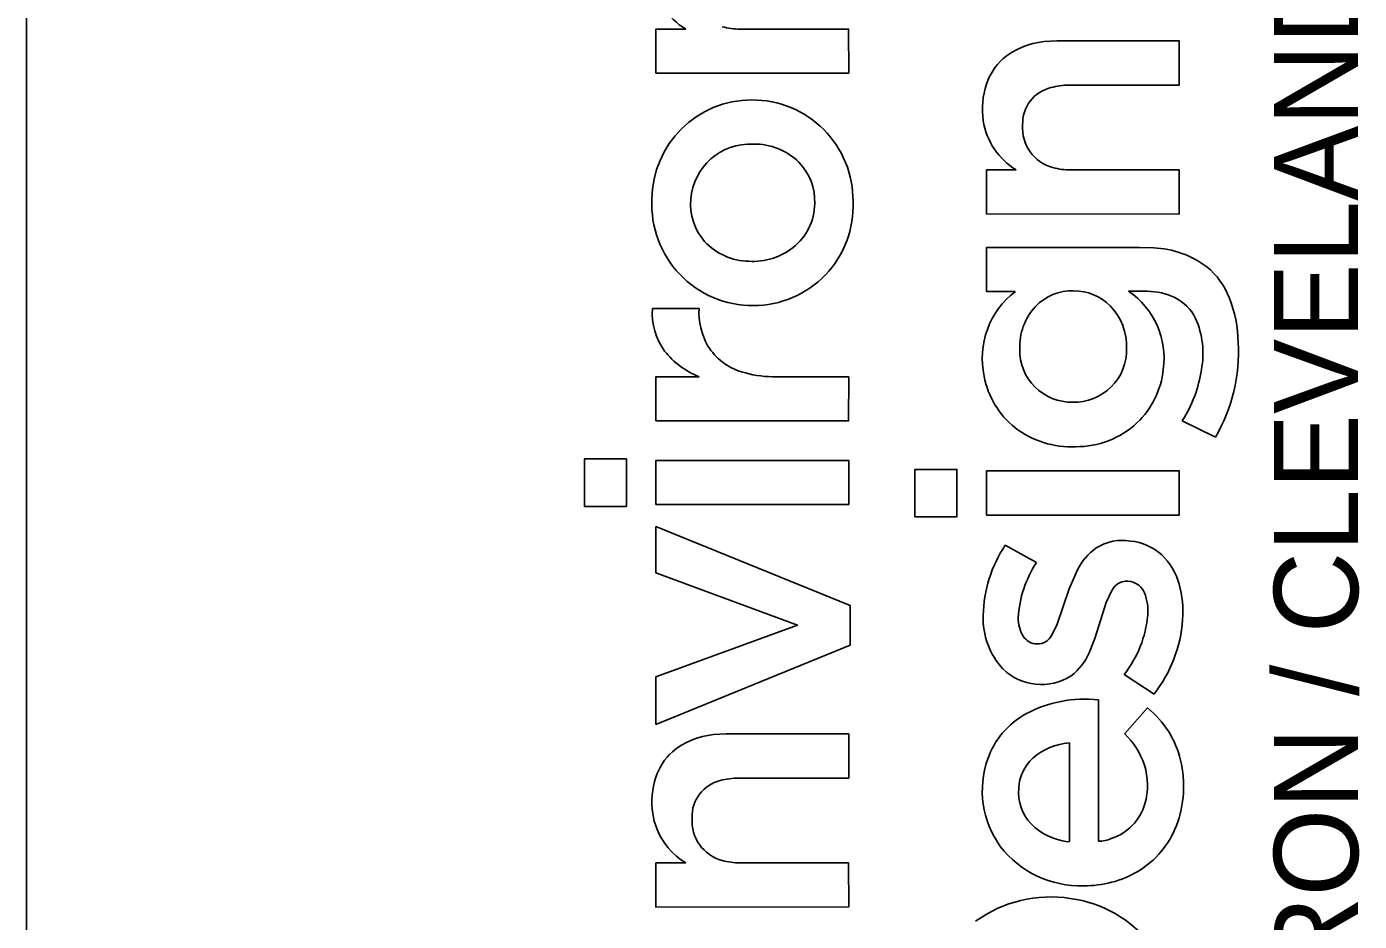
# Model space of a CAD drawing. Extents: x -0.2 to 34, y -0.5 to 22.
# Drawn here: x 32 to 32.901, y 2.778 to 3.382 of the extents above; entities that cross this region are included whole.
import ezdxf

# ---------------------------------------------------------------- set-up
doc = ezdxf.new("R2010")
doc.units = 0
doc.layers.add('SH_Border', color=7, linetype='Continuous')
doc.layers.add('SH_Data', color=7, linetype='Continuous')

msp = doc.modelspace()

# ---------------------------------------------------------------- linework, layer by layer
at = {"layer": 'SH_Border'}
msp.add_line((32, 0.5), (32, 21.5), dxfattribs=at)
at = {"layer": 'SH_Data'}
for p, q in [((32.42542, 3.38066), (32.44552, 3.38071)), ((32.42542, 3.35086), (32.42542, 3.38066)), ((32.48222, 3.38071), (32.55569, 3.38071)), ((32.55569, 3.38071), (32.55571, 3.35096)), ((32.68784, 3.3722), (32.69634, 3.37266)), ((32.69634, 3.37266), (32.77916, 3.37266)), ((32.77916, 3.37266), (32.77917, 3.34287)), ((32.55571, 3.35096), (32.42542, 3.35086)), ((32.77917, 3.34287), (32.70485, 3.3428)), ((32.64888, 3.2855), (32.66897, 3.28555)), ((32.64888, 3.25569), (32.64888, 3.2855)), ((32.70568, 3.28555), (32.77915, 3.28555)), ((32.77915, 3.28555), (32.77917, 3.25579)), ((32.77917, 3.25579), (32.64888, 3.25569)), ((32.6489, 3.20336), (32.64889, 3.23322)), ((32.64889, 3.23322), (32.75236, 3.23322)), ((32.75236, 3.23322), (32.76191, 3.23285)), ((32.66836, 3.20336), (32.6489, 3.20336)), ((32.75763, 3.20356), (32.74487, 3.20361)), ((32.42299, 3.19193), (32.45454, 3.19193)), ((32.42542, 3.14577), (32.45473, 3.14579)), ((32.42542, 3.11593), (32.42542, 3.14577)), ((32.50413, 3.14581), (32.55571, 3.14573)), ((32.55571, 3.14573), (32.55565, 3.11593)), ((32.55565, 3.11593), (32.42542, 3.11593)), ((32.8036, 3.10491), (32.7812, 3.11598)), ((32.37705, 3.05818), (32.37705, 3.09026)), ((32.37705, 3.09026), (32.40543, 3.09026)), ((32.40543, 3.09026), (32.40543, 3.05818)), ((32.42542, 3.05942), (32.42542, 3.08928)), ((32.42542, 3.08928), (32.55571, 3.08928)), ((32.55571, 3.08928), (32.55571, 3.05942)), ((32.60051, 3.05111), (32.60051, 3.08319)), ((32.60051, 3.08319), (32.62889, 3.08319)), ((32.62889, 3.08319), (32.62889, 3.05111)), ((32.64888, 3.05234), (32.64888, 3.0822)), ((32.64888, 3.0822), (32.77917, 3.0822)), ((32.77917, 3.0822), (32.77917, 3.05234)), ((32.40543, 3.05818), (32.37705, 3.05818)), ((32.55571, 3.05942), (32.42542, 3.05942)), ((32.62889, 3.05111), (32.60051, 3.05111)), ((32.77917, 3.05234), (32.64888, 3.05234)), ((32.42542, 3.01327), (32.42542, 3.0446)), ((32.42542, 3.0446), (32.5567, 2.9913)), ((32.66151, 3.03207), (32.68268, 3.02025)), ((32.52117, 2.97798), (32.42542, 3.01327)), ((32.70483, 3.00258), (32.71036, 3.01526)), ((32.69675, 2.97868), (32.70483, 3.00258)), ((32.73342, 3.00101), (32.72985, 2.9933)), ((32.5567, 2.9913), (32.5567, 2.96441)), ((32.72985, 2.9933), (32.72213, 2.96882)), ((32.42542, 2.94294), (32.52117, 2.97798)), ((32.69299, 2.97117), (32.69675, 2.97868)), ((32.5567, 2.96441), (32.42542, 2.91086)), ((32.72213, 2.96882), (32.71822, 2.95921)), ((32.42542, 2.91086), (32.42542, 2.94294)), ((32.76214, 2.93141), (32.74198, 2.94469)), ((32.72453, 2.92747), (32.72463, 2.83195)), ((32.74228, 2.90465), (32.75768, 2.922)), ((32.46439, 2.90397), (32.47289, 2.90443)), ((32.47289, 2.90443), (32.55571, 2.90443)), ((32.55571, 2.90443), (32.55571, 2.87465)), ((32.70489, 2.83182), (32.70489, 2.89834)), ((32.55571, 2.87465), (32.4814, 2.87457)), ((32.70361, 2.83165), (32.70489, 2.83182)), ((32.42542, 2.81728), (32.44552, 2.81733)), ((32.42542, 2.78747), (32.42542, 2.81728)), ((32.48222, 2.81733), (32.55569, 2.81733)), ((32.55569, 2.81733), (32.55571, 2.78756)), ((32.55571, 2.78756), (32.42542, 2.78747))]:
    msp.add_line(p, q, dxfattribs=at)
for points in [[(32.42542, 3.35086), (32.42542, 3.38066), (32.44552, 3.38071)], [(32.48222, 3.38071), (32.55569, 3.38071), (32.55571, 3.35096), (32.42542, 3.35086)], [(32.68784, 3.3722), (32.69634, 3.37266), (32.77916, 3.37266), (32.77917, 3.34287), (32.70485, 3.3428)], [(32.64888, 3.25569), (32.64888, 3.2855), (32.66897, 3.28555)], [(32.70568, 3.28555), (32.77915, 3.28555), (32.77917, 3.25579), (32.64888, 3.25569)], [(32.66836, 3.20336), (32.6489, 3.20336), (32.64889, 3.23322), (32.75236, 3.23322), (32.76191, 3.23285)], [(32.75763, 3.20356), (32.74487, 3.20361)], [(32.42299, 3.19193), (32.45454, 3.19193)], [(32.50413, 3.14581), (32.55571, 3.14573), (32.55565, 3.11593), (32.42542, 3.11593)], [(32.42542, 3.11593), (32.42542, 3.14577), (32.45473, 3.14579)], [(32.8036, 3.10491), (32.7812, 3.11598)], [(32.66151, 3.03207), (32.68268, 3.02025)], [(32.69299, 2.97117), (32.69675, 2.97868), (32.70483, 3.00258), (32.71036, 3.01526)], [(32.73342, 3.00101), (32.72985, 2.9933), (32.72213, 2.96882), (32.71822, 2.95921)], [(32.76214, 2.93141), (32.74198, 2.94469)], [(32.72453, 2.92747), (32.72463, 2.83195)], [(32.74228, 2.90465), (32.75768, 2.922)], [(32.46439, 2.90397), (32.47289, 2.90443), (32.55571, 2.90443), (32.55571, 2.87465), (32.4814, 2.87457)], [(32.70361, 2.83165), (32.70489, 2.83182), (32.70489, 2.89834)], [(32.42542, 2.78747), (32.42542, 2.81728), (32.44552, 2.81733)], [(32.48222, 2.81733), (32.55569, 2.81733), (32.55571, 2.78756), (32.42542, 2.78747)]]:
    msp.add_lwpolyline(points, dxfattribs=at)
for points in [[(32.37705, 3.05818), (32.37705, 3.09026), (32.40543, 3.09026), (32.40543, 3.05818)], [(32.42542, 3.05942), (32.42542, 3.08928), (32.55571, 3.08928), (32.55571, 3.05942)], [(32.60051, 3.05111), (32.60051, 3.08319), (32.62889, 3.08319), (32.62889, 3.05111)], [(32.64888, 3.05234), (32.64888, 3.0822), (32.77917, 3.0822), (32.77917, 3.05234)], [(32.42542, 2.91086), (32.42542, 2.94294), (32.52117, 2.97798), (32.42542, 3.01327), (32.42542, 3.0446), (32.5567, 2.9913), (32.5567, 2.96441)]]:
    msp.add_lwpolyline(points, close=True, dxfattribs=at)
for centre, radius, start, end in [((32.47027, 3.42141), 0.04763, 188.96462, 238.69865), ((32.47027, 3.42141), 0.04763, 188.96462, 238.69865), ((32.48183, 3.42286), 0.04215, 254.08913, 270.52838), ((32.48183, 3.42286), 0.04215, 254.08913, 270.52838), ((32.69216, 3.32251), 0.04988, 94.97056, 130.22484), ((32.69216, 3.32251), 0.04988, 94.97056, 130.22484), ((32.68694, 3.33085), 0.04016, 132.22383, 161.68229), ((32.68694, 3.33085), 0.04016, 132.22383, 161.68229), ((32.70217, 3.32642), 0.05602, 162.27398, 187.79173), ((32.70217, 3.32642), 0.05602, 162.27398, 187.79173), ((32.70453, 3.29679), 0.04601, 89.60515, 105.33026), ((32.70453, 3.29679), 0.04601, 89.60515, 105.33026), ((32.69828, 3.31689), 0.02498, 103.68683, 182.21395), ((32.69828, 3.31689), 0.02498, 103.68683, 182.21395), ((32.49014, 3.26543), 0.0674, 89.84756, 179.64047), ((32.49014, 3.26543), 0.0674, 89.84756, 179.64047), ((32.49057, 3.26474), 0.0681, 359.54009, 90.21138), ((32.49057, 3.26474), 0.0681, 359.54009, 90.21138), ((32.69372, 3.32624), 0.04763, 188.96462, 238.69865), ((32.69372, 3.32624), 0.04763, 188.96462, 238.69865), ((32.7008, 3.31381), 0.02757, 175.58441, 255.13816), ((32.7008, 3.31381), 0.02757, 175.58441, 255.13816), ((32.48923, 3.26263), 0.0404, 87.04809, 175.57259), ((32.48923, 3.26263), 0.0404, 87.04809, 175.57259), ((32.49204, 3.25999), 0.04299, 45.84264, 90.98008), ((32.49204, 3.25999), 0.04299, 45.84264, 90.98008), ((32.49458, 3.26421), 0.03821, 357.88569, 44.15902), ((32.49458, 3.26421), 0.03821, 357.88569, 44.15902), ((32.70529, 3.32769), 0.04215, 254.08913, 270.52838), ((32.70529, 3.32769), 0.04215, 254.08913, 270.52838), ((32.49083, 3.26209), 0.06819, 176.8344, 270.40384), ((32.49083, 3.26209), 0.06819, 176.8344, 270.40384), ((32.48729, 3.2625), 0.03848, 175.15378, 221.14706), ((32.48729, 3.2625), 0.03848, 175.15378, 221.14706), ((32.49123, 3.26139), 0.06749, 270.06243, 2.37759), ((32.49123, 3.26139), 0.06749, 270.06243, 2.37759), ((32.49446, 3.26318), 0.0383, 308.28936, 359.43468), ((32.49446, 3.26318), 0.0383, 308.28936, 359.43468), ((32.48919, 3.26607), 0.04228, 223.09994, 268.80895), ((32.48919, 3.26607), 0.04228, 223.09994, 268.80895), ((32.49096, 3.2679), 0.04418, 266.56515, 308.06078), ((32.49096, 3.2679), 0.04418, 266.56515, 308.06078), ((32.75907, 3.16789), 0.06503, 53.40344, 87.49062), ((32.75907, 3.16789), 0.06503, 53.40344, 87.49062), ((32.76517, 3.18039), 0.05141, 21.60748, 50.5577), ((32.76517, 3.18039), 0.05141, 21.60748, 50.5577), ((32.70292, 3.15813), 0.05692, 127.37482, 192.22468), ((32.70292, 3.15813), 0.05692, 127.37482, 192.22468), ((32.70693, 3.16927), 0.0346, 88.47302, 136.42562), ((32.70693, 3.16927), 0.0346, 88.47302, 136.42562), ((32.70814, 3.16963), 0.03424, 44.27195, 90.47623), ((32.70814, 3.16963), 0.03424, 44.27195, 90.47623), ((32.71421, 3.15829), 0.05472, 352.1125, 55.92295), ((32.71421, 3.15829), 0.05472, 352.1125, 55.92295), ((32.75666, 3.15725), 0.04633, 65.01687, 88.8011), ((32.75666, 3.15725), 0.04633, 65.01687, 88.8011), ((32.7626, 3.17155), 0.03085, 26.26808, 63.80301), ((32.7626, 3.17155), 0.03085, 26.26808, 63.80301), ((32.73069, 3.16714), 0.08835, 1.15143, 21.3627), ((32.73069, 3.16714), 0.08835, 1.15143, 21.3627), ((32.46616, 3.18882), 0.04329, 175.87313, 216.34747), ((32.46616, 3.18882), 0.04329, 175.87313, 216.34747), ((32.50087, 3.18948), 0.04639, 176.9688, 209.60636), ((32.50087, 3.18948), 0.04639, 176.9688, 209.60636), ((32.71141, 3.16602), 0.0401, 137.46739, 182.33237), ((32.71141, 3.16602), 0.0401, 137.46739, 182.33237), ((32.70368, 3.166), 0.03996, 358.57141, 43.53765), ((32.70368, 3.166), 0.03996, 358.57141, 43.53765), ((32.73565, 3.16154), 0.05953, 349.30734, 23.43071), ((32.73565, 3.16154), 0.05953, 349.30734, 23.43071), ((32.47466, 3.19716), 0.05511, 218.09809, 248.7907), ((32.47466, 3.19716), 0.05511, 218.09809, 248.7907), ((32.49514, 3.18814), 0.04079, 211.94466, 253.2028), ((32.49514, 3.18814), 0.04079, 211.94466, 253.2028), ((32.70645, 3.1637), 0.03511, 178.88208, 271.08374), ((32.70645, 3.1637), 0.03511, 178.88208, 271.08374), ((32.70818, 3.16404), 0.03546, 268.27882, 1.55016), ((32.70818, 3.16404), 0.03546, 268.27882, 1.55016), ((32.70538, 3.16244), 0.11383, 329.6388, 3.25998), ((32.70538, 3.16244), 0.11383, 329.6388, 3.25998), ((32.50465, 3.2165), 0.07069, 252.46555, 269.57296), ((32.50465, 3.2165), 0.07069, 252.46555, 269.57296), ((32.70463, 3.15696), 0.05837, 190.75182, 231.28919), ((32.70463, 3.15696), 0.05837, 190.75182, 231.28919), ((32.70988, 3.15708), 0.05887, 313.74196, 353.8554), ((32.70988, 3.15708), 0.05887, 313.74196, 353.8554), ((32.70738, 3.16334), 0.08771, 327.31495, 351.57478), ((32.70738, 3.16334), 0.08771, 327.31495, 351.57478), ((32.70632, 3.16112), 0.06269, 232.46061, 272.59022), ((32.70632, 3.16112), 0.06269, 232.46061, 272.59022), ((32.70954, 3.15901), 0.06051, 269.6361, 312.70877), ((32.70954, 3.15901), 0.06051, 269.6361, 312.70877), ((32.73636, 2.98258), 0.08973, 146.53104, 178.7571), ((32.73636, 2.98258), 0.08973, 146.53104, 178.7571), ((32.74661, 2.99713), 0.04053, 125.51182, 153.41595), ((32.74661, 2.99713), 0.04053, 125.51182, 153.41595), ((32.7406, 3.0026), 0.03263, 80.17192, 122.51969), ((32.7406, 3.0026), 0.03263, 80.17192, 122.51969), ((32.74278, 2.99824), 0.03667, 47.79344, 84.68918), ((32.74278, 2.99824), 0.03667, 47.79344, 84.68918), ((32.74519, 2.9789), 0.07495, 146.51121, 176.91007), ((32.74519, 2.9789), 0.07495, 146.51121, 176.91007), ((32.73788, 2.9946), 0.04267, 14.9966, 46.20632), ((32.73788, 2.9946), 0.04267, 14.9966, 46.20632), ((32.74384, 2.99631), 0.01143, 76.66094, 155.7053), ((32.74384, 2.99631), 0.01143, 76.66094, 155.7053), ((32.74397, 2.99511), 0.01256, 21.5098, 78.52618), ((32.74397, 2.99511), 0.01256, 21.5098, 78.52618), ((32.71044, 2.98674), 0.07121, 355.83062, 15.39138), ((32.71044, 2.98674), 0.07121, 355.83062, 15.39138), ((32.72592, 2.98766), 0.03209, 354.57264, 22.06805), ((32.72592, 2.98766), 0.03209, 354.57264, 22.06805), ((32.69666, 2.98238), 0.05005, 177.53659, 222.79318), ((32.69666, 2.98238), 0.05005, 177.53659, 222.79318), ((32.6931, 2.98233), 0.02276, 178.47474, 211.08679), ((32.6931, 2.98233), 0.02276, 178.47474, 211.08679), ((32.68248, 2.99149), 0.0757, 321.81101, 354.79685), ((32.68248, 2.99149), 0.0757, 321.81101, 354.79685), ((32.68952, 2.9882), 0.09219, 321.9777, 355.87384), ((32.68952, 2.9882), 0.09219, 321.9777, 355.87384), ((32.68331, 2.9767), 0.01148, 212.23676, 268.37769), ((32.68331, 2.9767), 0.01148, 212.23676, 268.37769), ((32.68342, 2.97589), 0.01067, 267.71603, 333.73375), ((32.68342, 2.97589), 0.01067, 267.71603, 333.73375), ((32.68098, 2.9758), 0.04077, 308.08772, 335.98736), ((32.68098, 2.9758), 0.04077, 308.08772, 335.98736), ((32.68599, 2.97535), 0.0375, 225.98539, 302.47965), ((32.68599, 2.97535), 0.0375, 225.98539, 302.47965), ((32.7152, 2.84414), 0.08384, 83.61499, 118.28755), ((32.7152, 2.84414), 0.08384, 83.61499, 118.28755), ((32.71744, 2.87167), 0.06443, 13.53365, 51.36148), ((32.71744, 2.87167), 0.06443, 13.53365, 51.36148), ((32.70239, 2.86906), 0.05583, 118.83082, 160.62438), ((32.70239, 2.86906), 0.05583, 118.83082, 160.62438), ((32.46871, 2.85428), 0.04988, 94.96958, 130.22249), ((32.46871, 2.85428), 0.04988, 94.96958, 130.22249), ((32.70378, 2.86556), 0.05486, 19.03571, 45.44059), ((32.70378, 2.86556), 0.05486, 19.03571, 45.44059), ((32.46348, 2.86263), 0.04015, 132.22192, 161.68183), ((32.46348, 2.86263), 0.04015, 132.22192, 161.68183), ((32.70785, 2.85609), 0.04235, 94.00805, 130.88169), ((32.70785, 2.85609), 0.04235, 94.00805, 130.88169), ((32.71041, 2.86612), 0.06437, 160.52012, 215.78311), ((32.71041, 2.86612), 0.06437, 160.52012, 215.78311), ((32.70048, 2.86628), 0.02985, 132.98507, 177.179), ((32.70048, 2.86628), 0.02985, 132.98507, 177.179), ((32.71069, 2.8697), 0.047, 344.60586, 17.007), ((32.71069, 2.8697), 0.047, 344.60586, 17.007), ((32.70635, 2.86921), 0.07579, 339.3542, 13.37853), ((32.70635, 2.86921), 0.07579, 339.3542, 13.37853), ((32.47872, 2.85819), 0.05601, 162.27355, 187.79185), ((32.47872, 2.85819), 0.05601, 162.27355, 187.79185), ((32.48108, 2.82856), 0.04601, 89.60494, 105.3284), ((32.48108, 2.82856), 0.04601, 89.60494, 105.3284), ((32.47482, 2.84867), 0.02498, 103.68646, 182.21874), ((32.47482, 2.84867), 0.02498, 103.68646, 182.21874), ((32.7017, 2.86503), 0.03115, 175.00126, 223.28301), ((32.7017, 2.86503), 0.03115, 175.00126, 223.28301), ((32.7224, 2.86715), 0.03504, 288.00773, 343.55078), ((32.7224, 2.86715), 0.03504, 288.00773, 343.55078), ((32.47026, 2.85802), 0.04762, 188.96199, 238.70369), ((32.47026, 2.85802), 0.04762, 188.96199, 238.70369), ((32.47735, 2.84558), 0.02756, 175.58538, 255.14386), ((32.47735, 2.84558), 0.02756, 175.58538, 255.14386), ((32.70891, 2.87363), 0.04231, 225.06188, 262.79738), ((32.70891, 2.87363), 0.04231, 225.06188, 262.79738), ((32.71894, 2.8652), 0.0626, 300.94269, 338.73225), ((32.71894, 2.8652), 0.0626, 300.94269, 338.73225), ((32.72474, 2.85216), 0.02021, 269.7003, 294.8711), ((32.72474, 2.85216), 0.02021, 269.7003, 294.8711), ((32.71253, 2.87054), 0.06872, 217.74516, 271.65431), ((32.71253, 2.87054), 0.06872, 217.74516, 271.65431), ((32.48183, 2.85948), 0.04215, 254.09162, 270.52835), ((32.48183, 2.85948), 0.04215, 254.09162, 270.52835), ((32.71549, 2.87241), 0.07056, 269.20477, 300.33412), ((32.71549, 2.87241), 0.07056, 269.20477, 300.33412), ((32.69229, 2.70792), 0.08641, 81.19402, 125.99844), ((32.69229, 2.70792), 0.08641, 81.19402, 125.99844), ((32.69458, 2.71132), 0.08272, 37.85208, 82.40204), ((32.69458, 2.71132), 0.08272, 37.85208, 82.40204)]:
    msp.add_arc(centre, radius, start, end, dxfattribs=at)

# ---------------------------------------------------------------- texts
msp.add_text('AKRON / CLEVELAND / COLUMBUS', height=0.056969, rotation=90, dxfattribs=at).set_placement((32.90012, 2.638))

doc.saveas('drawing.dxf')
